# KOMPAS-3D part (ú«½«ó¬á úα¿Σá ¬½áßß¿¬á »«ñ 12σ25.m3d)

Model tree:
1. Эскиз:1
2. Операция выдавливания:2
     Расстояние 1 = 130
3. Эскиз:2
4. Вырезать элемент выдавливания:1
     Расстояние 1 = 20
5. Операция выдавливания:3
     Расстояние 1 = 40
6. Эскиз:3
7. Вырезать элемент выдавливания:2
     Расстояние 2 = 15; Расстояние 1 = 20
8. Эскиз:4
9. Вырезать элемент выдавливания:3
     Расстояние 2 = 15; Расстояние 1 = 20
10. Скругление:1
     Радиус = 5
11. Скругление:2
     Радиус = 5
12. Скругление:3
     Радиус = 5
13. Скругление:4
     Радиус = 5
14. Скругление:5
     Радиус = 5
15. Скругление:6
     Радиус = 5
16. Скругление:7
     Радиус = 5
17. Скругление:8
     Радиус = 5
18. Скругление:9
     Радиус = 5
19. Скругление:10
     Радиус = 5
20. Эскиз:6
21. Вырезать элемент выдавливания:4
     Расстояние 2 = 15; Расстояние 1 = 110
22. Эскиз:7
23. Операция выдавливания:4
     Расстояние 1 = 40
24. Эскиз:8
25. Операция выдавливания:5
     Расстояние 1 = 40; Расстояние 2 = 5
26. Скругление:13
     Радиус = 2
27. Скругление:14
     Радиус = 2
28. Скругление:15
     Радиус = 2
29. Скругление:16
     Радиус = 2
30. Эскиз:9
31. Вырезать элемент выдавливания:5
     Расстояние 1 = 170
